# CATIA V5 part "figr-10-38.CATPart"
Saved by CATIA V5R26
Part number: Part1
Bounding box of the stored display mesh (mm): x -94.328 to 61.591, y -127.491 to 0, z 0 to 176.047
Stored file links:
  D:\_Deepak\CATIA\CATIA V5 2015 Parts Files\Part files\Partfiles\c10_catia_v5_6r2015_prt\figr-10-36.CATPart
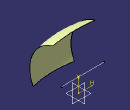
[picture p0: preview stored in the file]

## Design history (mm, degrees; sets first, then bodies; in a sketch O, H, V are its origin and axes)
Body1 (main body)
  Sketch1 on zx-plane, origin (0, 0, 0), H (-1, 0, 0), V (0, 0, 1)
    line L1 (-61.5909, 52.3674) -> (94.3285, 52.3674)
    horizontal: L1 H
  Sketch2 on xy-plane, origin (0, 0, 0), H (1, 0, 0), V (0, 1, 0)
    spline S1 through (-163.8621, -89.1589) (-19.9449, -116.4274) (134.5767, -79.3119)
  Sweep1: type Circle, Guide Sketch1, Radius 100, Angle1 0, Angle2 100, Reference Sketch2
